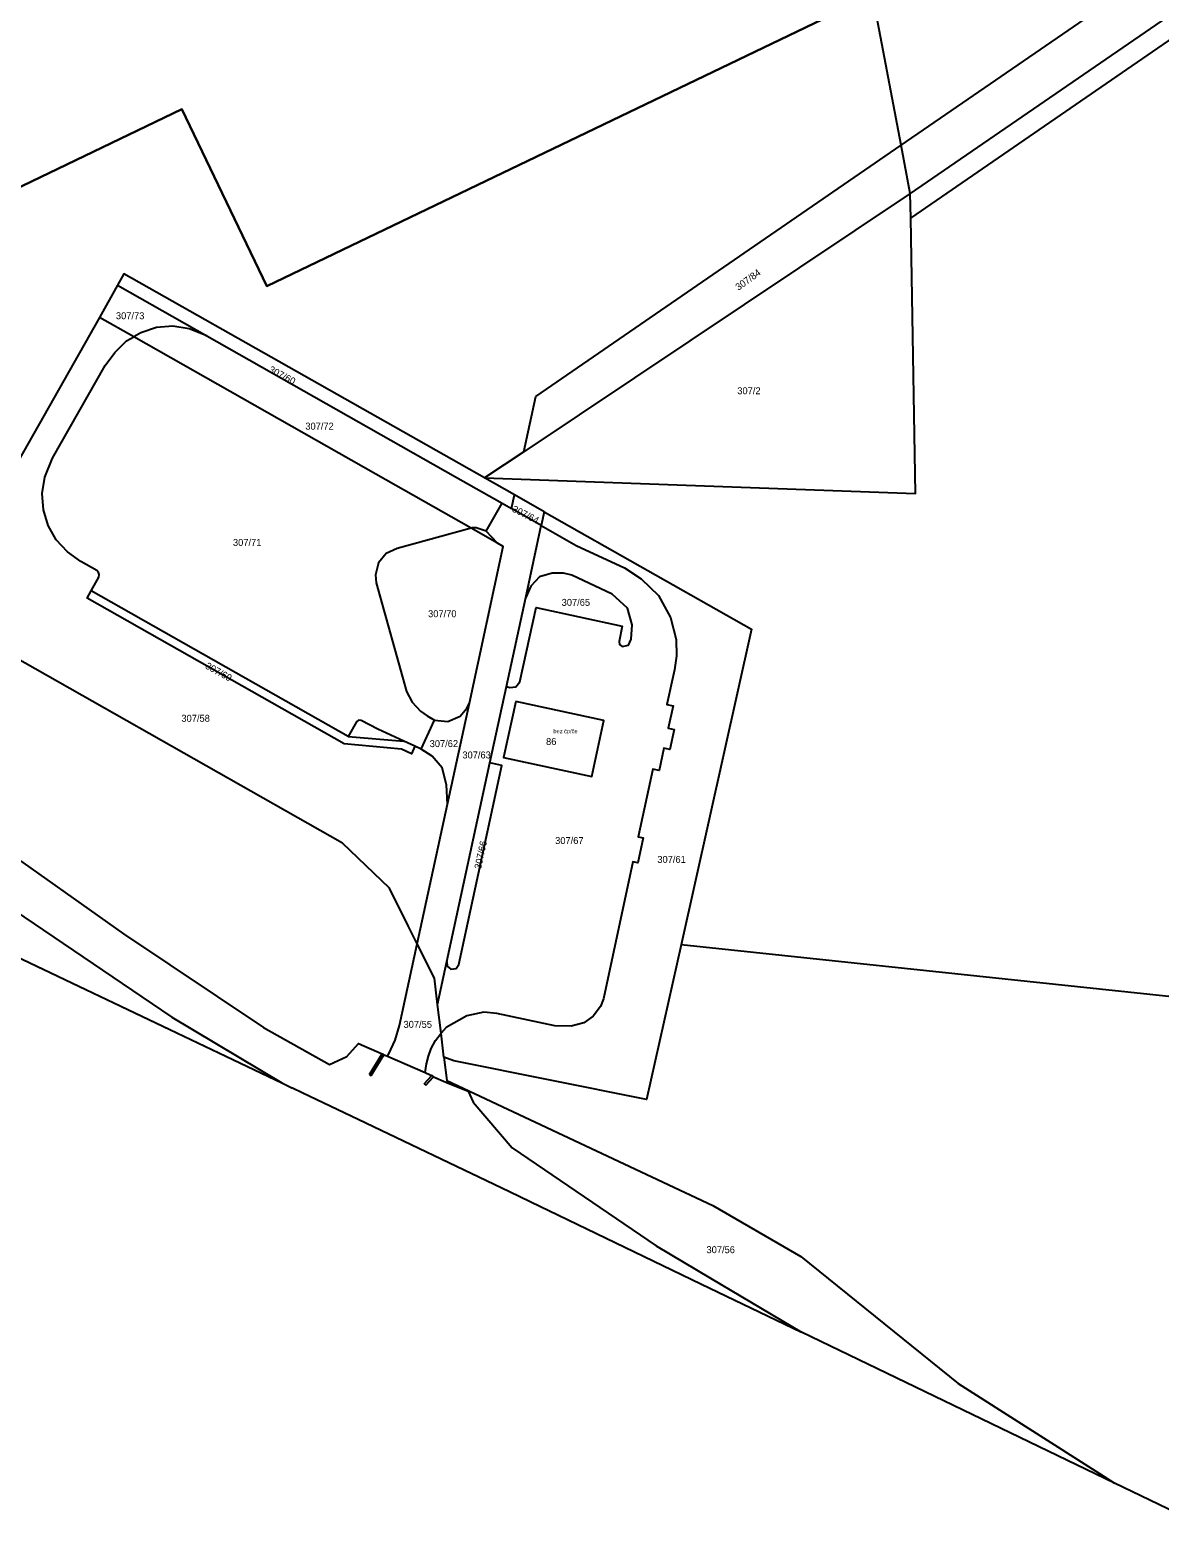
# Model space of a CAD drawing. Extents: x -882150 to -879379, y -1022570 to -1019819.
# Drawn here: x -881773.8 to -881497.7, y -1022369.8 to -1022001.3 of the extents above; entities that cross this region are included whole.
import ezdxf

# ---------------------------------------------------------------- set-up
doc = ezdxf.new("R2010")
doc.units = 0
for name, color, linetype in [('Definiční body', 7, 'Continuous'), ('Hranice parcel', 7, 'Continuous'), ('Parcelní čísla', 7, 'Continuous'), ('Polygon budovy', 7, 'Continuous'), ('Vnitřní kresba', 7, 'Continuous')]:
    doc.layers.add(name, color=color, linetype=linetype)

msp = doc.modelspace()

# ---------------------------------------------------------------- linework, layer by layer
at = {"layer": 'Hranice parcel'}
for p, q in [((-881558.61, -1022047.23), (-881425.79, -1021955.96)), ((-881560.95, -1022029.43), (-881567.9, -1021992.66)), ((-881558.72, -1022041.24), (-881560.95, -1022029.43)), ((-881558.72, -1022041.24), (-881653.2, -1022104.35)), ((-881558.61, -1022047.23), (-881558.72, -1022041.24)), ((-881752.46, -1022063.65), (-881756.89, -1022071.5)), ((-881752.46, -1022063.65), (-881730.66, -1022076.01)), ((-881756.89, -1022071.5), (-881776.79, -1022106.66)), ((-881748.47, -1022076.28), (-881756.89, -1022071.5)), ((-881653.2, -1022104.35), (-881662.78, -1022110.75)), ((-881655.48, -1022114.89), (-881662.78, -1022110.75)), ((-881658.5, -1022116.94), (-881656.2, -1022118.24)), ((-881656.2, -1022118.24), (-881655.48, -1022114.89)), ((-881648.18, -1022119.01), (-881655.48, -1022114.89)), ((-881648.91, -1022122.38), (-881656.2, -1022118.24)), ((-881648.18, -1022119.01), (-881648.91, -1022122.38)), ((-881659.6, -1022126.68), (-881666.03, -1022123.03)), ((-881652.71, -1022139.94), (-881648.91, -1022122.38)), ((-881657.43, -1022161.75), (-881652.71, -1022139.94)), ((-881661.45, -1022180.33), (-881657.43, -1022161.75)), ((-881671.82, -1022190.45), (-881666.48, -1022165.78)), ((-881678.28, -1022177.02), (-881674.99, -1022169.9)), ((-881678.28, -1022177.02), (-881679.79, -1022176.32)), ((-881671.96, -1022228.89), (-881661.45, -1022180.33)), ((-881679.2, -1022224.6), (-881671.82, -1022190.45)), ((-881779.05, -1022226.8), (-881712.33, -1022258.57)), ((-881674.23, -1022239.39), (-881671.96, -1022228.89)), ((-881673.39, -1022246.43), (-881674.23, -1022239.39)), ((-881672.69, -1022252.25), (-881673.39, -1022246.43)), ((-881686.51, -1022252.07), (-881677.28, -1022256.05)), ((-881712.33, -1022258.57), (-881709.85, -1022259.75)), ((-881691.82, -1022268.34), (-881660.45, -1022283.35)), ((-881649.13, -1022288.77), (-881647.05, -1022289.76)), ((-881647.05, -1022289.76), (-881609.91, -1022307.65)), ((-881609.91, -1022307.65), (-881585.3, -1022319.51)), ((-881508.76, -1022356.39), (-881585.3, -1022319.51)), ((-881481.01, -1022369.75), (-881508.76, -1022356.39))]:
    msp.add_line(p, q, dxfattribs=at)
for points in [[(-881567.9, -1021992.66), (-881715.98, -1022063.86), (-881736.79, -1022020.61), (-881801.66, -1022051.83), (-881843.65, -1021964.47), (-881753.54, -1021921.14), (-881615.78, -1021854.9), (-881579.78, -1021929.76)], [(-881560.95, -1022029.43), (-881479.31, -1021973.32), (-881396.89, -1021916.68)], [(-881390.66, -1021925.75), (-881405.65, -1021936.05), (-881558.72, -1022041.24)], [(-881982.3, -1022007.45), (-881977.44, -1022017.7), (-881964.57, -1022038.79), (-881958.6, -1022045.96), (-881931.45, -1022071.52), (-881904.65, -1022096), (-881883.63, -1022114.91), (-881867, -1022129.86), (-881850.56, -1022145.58), (-881825.95, -1022166.69), (-881802.82, -1022185.46), (-881751.05, -1022222.15), (-881716.76, -1022245.07), (-881700.7, -1022254.05), (-881696.42, -1022252.15), (-881693.58, -1022248.92), (-881687.79, -1022251.45), (-881687.36, -1022251.71), (-881686.91, -1022251.9), (-881686.51, -1022252.07)], [(-881653.2, -1022104.35), (-881650.27, -1022090.81), (-881560.95, -1022029.43)], [(-881662.78, -1022110.75), (-881557.43, -1022114.54), (-881558.61, -1022047.23)], [(-881662.78, -1022110.75), (-881750.9, -1022060.9), (-881752.46, -1022063.65)], [(-881730.66, -1022076.01), (-881734.97, -1022074.27), (-881738.97, -1022073.65), (-881742.95, -1022073.99), (-881746.74, -1022075.32), (-881748.47, -1022076.28)], [(-881758.91, -1022138.37), (-881757.04, -1022135), (-881756.96, -1022134.35), (-881757.11, -1022133.88), (-881757.53, -1022133.38), (-881761.47, -1022131.15), (-881764.7, -1022128.79), (-881767.46, -1022125.88), (-881769.42, -1022122.37), (-881770.6, -1022118.54), (-881770.87, -1022114.54), (-881770.22, -1022110.55), (-881768.35, -1022105.92), (-881755.53, -1022083.3), (-881753.11, -1022080.09), (-881750.26, -1022077.27), (-881748.47, -1022076.28)], [(-881666.03, -1022123.03), (-881689.35, -1022109.8), (-881748.47, -1022076.28)], [(-881730.66, -1022076.01), (-881669.86, -1022110.5), (-881658.5, -1022116.94)], [(-881659.6, -1022126.68), (-881662.39, -1022123.78), (-881658.5, -1022116.94)], [(-881648.18, -1022119.01), (-881597.5, -1022147.69), (-881614.74, -1022224.86)], [(-881666.03, -1022123.03), (-881684.12, -1022127.98), (-881686.82, -1022129.24), (-881688.69, -1022131.53), (-881689.42, -1022134.42), (-881689.22, -1022136.4), (-881681.82, -1022162.93), (-881680.42, -1022165.57), (-881678.38, -1022167.7), (-881676.77, -1022168.88), (-881674.99, -1022169.9)], [(-881648.91, -1022122.38), (-881640.38, -1022127.23), (-881628.59, -1022132.72), (-881624.48, -1022135.41), (-881620.26, -1022139.51), (-881617.32, -1022144.86), (-881615.94, -1022150.21), (-881615.86, -1022154.23), (-881616.36, -1022157.65), (-881618.18, -1022166.1), (-881616.7, -1022166.42), (-881617.88, -1022171.89), (-881616.41, -1022172.21), (-881617.47, -1022177.09), (-881618.94, -1022176.78), (-881620.12, -1022182.25), (-881621.6, -1022181.93), (-881625.18, -1022198.46), (-881623.99, -1022198.71), (-881625.3, -1022204.77), (-881626.49, -1022204.52), (-881633.73, -1022238), (-881634.45, -1022239.88), (-881636.22, -1022242.27), (-881638.52, -1022243.87), (-881641.63, -1022244.69), (-881645.55, -1022244.63), (-881659.76, -1022241.6), (-881662.95, -1022241.31), (-881667.09, -1022242.15), (-881672.17, -1022245.05), (-881673.39, -1022246.43)], [(-881666.48, -1022165.78), (-881658.2, -1022127.47), (-881659.6, -1022126.68)], [(-881657.43, -1022161.75), (-881656.6, -1022161.92), (-881655.13, -1022161.78), (-881654.15, -1022160.61), (-881650.15, -1022142.41), (-881629.1, -1022146.95), (-881629.9, -1022150.72), (-881629.76, -1022151.47), (-881629.1, -1022151.91), (-881627.62, -1022151.59), (-881626.91, -1022150.13), (-881626.68, -1022146.66), (-881627.82, -1022142.6), (-881631.57, -1022139.17), (-881641.47, -1022134.54), (-881643.47, -1022134.05), (-881646.23, -1022134.03), (-881649.35, -1022134.94), (-881651.43, -1022137.17), (-881652.71, -1022139.94)], [(-881679.79, -1022176.32), (-881680.63, -1022178.14), (-881683.05, -1022177.03), (-881697.07, -1022175.68), (-881759.89, -1022140.11), (-881758.91, -1022138.37)], [(-881679.79, -1022176.32), (-881682.52, -1022175.07), (-881688.88, -1022172.15), (-881692.92, -1022170.01), (-881693.57, -1022169.95), (-881694.08, -1022170.37), (-881696.08, -1022173.94), (-881758.91, -1022138.37)], [(-881679.2, -1022224.6), (-881681.33, -1022220.34), (-881686, -1022211), (-881697.5, -1022200), (-881797.52, -1022143.3)], [(-881674.99, -1022169.9), (-881671.7, -1022170.24), (-881668.7, -1022168.95), (-881667.06, -1022166.98), (-881666.48, -1022165.78)], [(-881655.16, -1022165.38), (-881658.15, -1022179.09), (-881636.58, -1022183.73), (-881633.6, -1022170), (-881655.16, -1022165.38)], [(-881671.82, -1022190.45), (-881672.05, -1022185.7), (-881673.16, -1022181.55), (-881675.55, -1022178.75), (-881678.28, -1022177.02)], [(-881671.96, -1022228.89), (-881671.87, -1022230.05), (-881671.03, -1022230.79), (-881669.73, -1022230.64), (-881669.05, -1022229.65), (-881658.57, -1022181.01), (-881661.45, -1022180.33)], [(-881686.51, -1022252.07), (-881686.18, -1022251.5), (-881684.59, -1022248.14), (-881683.53, -1022244.59), (-881679.2, -1022224.6)], [(-881674.23, -1022239.39), (-881675, -1022233), (-881679.2, -1022224.6)], [(-881614.74, -1022224.86), (-881623.19, -1022262.67), (-881670.27, -1022253.22), (-881672.69, -1022252.25)], [(-881371.85, -1022246.68), (-881420.94, -1022245.39), (-881614.74, -1022224.86)], [(-881677.28, -1022256.05), (-881676.93, -1022253.93), (-881676.49, -1022252.03), (-881675.8, -1022250.17), (-881674.76, -1022248.25), (-881673.39, -1022246.43)], [(-881672.69, -1022252.25), (-881672, -1022258), (-881607, -1022288.5), (-881585.5, -1022301), (-881547, -1022332), (-881512.5, -1022354), (-881508.76, -1022356.39)], [(-881677.28, -1022256.05), (-881676.95, -1022256.19), (-881675.62, -1022256.77), (-881675.25, -1022257.12), (-881672.24, -1022258.36), (-881668.83, -1022259.78), (-881666.78, -1022260.63), (-881665.54, -1022263.32), (-881656.05, -1022274.46), (-881620.85, -1022298.41), (-881607.54, -1022306.31), (-881585.3, -1022319.51)], [(-881709.85, -1022259.75), (-881709.71, -1022259.82), (-881707.35, -1022260.94), (-881691.82, -1022268.34)], [(-881660.45, -1022283.35), (-881656.69, -1022285.15), (-881649.13, -1022288.77)]]:
    msp.add_lwpolyline(points, dxfattribs=at)
at = {"layer": 'Polygon budovy'}
for points in [[(-881753.54, -1021921.14), (-881843.65, -1021964.47), (-881801.66, -1022051.83), (-881736.79, -1022020.61), (-881715.98, -1022063.86), (-881567.9, -1021992.66), (-881552.98, -1021985.49), (-881579.78, -1021929.76), (-881615.78, -1021854.9)], [(-881655.16, -1022165.38), (-881658.15, -1022179.09), (-881636.58, -1022183.73), (-881633.6, -1022170)]]:
    msp.add_lwpolyline(points, close=True, dxfattribs=at)
at = {"layer": 'Vnitřní kresba'}
for p, q in [((-881696.08, -1022173.94), (-881682.52, -1022175.07)), ((-881780.22, -1022214.7), (-881739.24, -1022242.53)), ((-881739.24, -1022242.53), (-881712.33, -1022258.57)), ((-881690.89, -1022256.52), (-881687.79, -1022251.45)), ((-881690.45, -1022256.78), (-881687.36, -1022251.71)), ((-881690.89, -1022256.52), (-881690.45, -1022256.78)), ((-881677.52, -1022258.82), (-881675.62, -1022256.77)), ((-881677.15, -1022259.16), (-881675.25, -1022257.12)), ((-881677.52, -1022258.82), (-881677.15, -1022259.16))]:
    msp.add_line(p, q, dxfattribs=at)
msp.add_lwpolyline([(-881662.39, -1022123.78), (-881663.84, -1022123.24), (-881664.85, -1022122.97), (-881665.82, -1022122.97), (-881666.03, -1022123.03)], dxfattribs=at)

# ---------------------------------------------------------------- texts
at = {"layer": 'Definiční body'}
msp.add_text('bez čp/če', height=1, dxfattribs=at).set_placement((-881645.93, -1022173.13))
at = {"layer": 'Parcelní čísla'}
for s, rotation, p in [('307/84', 36, (-881600.698, -1022065.026)), ('307/60', 332, (-881715.679, -1022084.78)), ('307/64', 333, (-881656.198, -1022118.878)), ('307/69', 331, (-881731.194, -1022157.179)), ('307/66', 78, (-881663.62, -1022206.432))]:
    msp.add_text(s, height=1.7, rotation=rotation, dxfattribs=at).set_placement(p)
for s, p in [('307/73', (-881752.861, -1022071.96)), ('307/2', (-881600.99, -1022090.29)), ('307/72', (-881706.575, -1022098.94)), ('307/71', (-881724.261, -1022127.36)), ('307/70', (-881676.568, -1022144.78)), ('307/65', (-881643.927, -1022142)), ('307/58', (-881736.862, -1022170.33)), ('307/62', (-881676.185, -1022176.52)), ('86', (-881647.731, -1022176)), ('307/63', (-881668.191, -1022179.29)), ('307/67', (-881645.518, -1022200.21)), ('307/61', (-881620.531, -1022204.82)), ('307/55', (-881682.57, -1022245.12)), ('307/56', (-881608.52, -1022300.18))]:
    msp.add_text(s, height=1.7, dxfattribs=at).set_placement(p)

doc.saveas('drawing.dxf')
